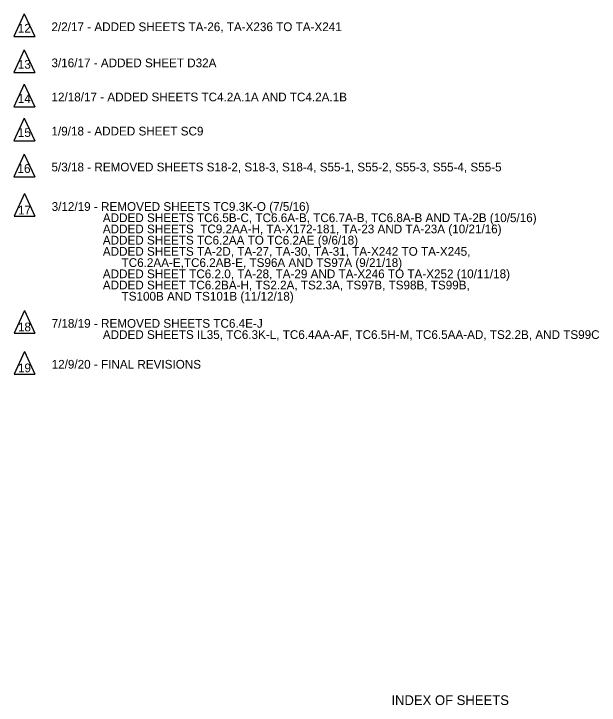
# Model space of a CAD drawing. Extents: x 116 to 2310, y 9 to 1131.
# Drawn here: x 1337.6 to 1756.2, y 112.9 to 607.5 of the extents above; entities that cross this region are included whole.
import ezdxf

# ---------------------------------------------------------------- set-up
doc = ezdxf.new("R2010")
doc.units = 0
for name, color, linetype in [('BR_AUTO DIMENSION', 7, 'Continuous'), ('BR_TEXT', 7, 'Continuous'), ('RD_SHT_TX', 7, 'Continuous'), ('RD_TX_RoadID', 7, 'Continuous')]:
    doc.layers.add(name, color=color, linetype=linetype)

msp = doc.modelspace()

# ---------------------------------------------------------------- linework, layer by layer
at = {"layer": 'BR_AUTO DIMENSION'}
for p, q in [((1345.07, 607.5), (1337.57, 591.27)), ((1345.07, 607.5), (1352.57, 591.27)), ((1337.57, 591.27), (1352.57, 591.27)), ((1345.07, 581.67), (1337.57, 565.43)), ((1345.07, 581.67), (1352.57, 565.43)), ((1337.57, 565.43), (1352.57, 565.43)), ((1345.07, 557.26), (1337.57, 541.02)), ((1345.07, 557.26), (1352.57, 541.02)), ((1337.57, 541.02), (1352.57, 541.02)), ((1345.07, 532.86), (1337.57, 516.62)), ((1345.07, 532.86), (1352.57, 516.62)), ((1337.57, 516.62), (1352.57, 516.62)), ((1345.07, 507.16), (1337.57, 490.92)), ((1345.07, 507.16), (1352.57, 490.92)), ((1337.57, 490.92), (1352.57, 490.92)), ((1345.2, 478.9), (1337.7, 462.67)), ((1345.2, 478.9), (1352.7, 462.67)), ((1337.7, 462.67), (1352.7, 462.67)), ((1345.2, 395.29), (1337.7, 379.05)), ((1345.2, 395.29), (1352.7, 379.05)), ((1337.7, 379.05), (1352.7, 379.05)), ((1345.2, 366.01), (1337.7, 349.78)), ((1345.2, 366.01), (1352.7, 349.78)), ((1337.7, 349.78), (1352.7, 349.78))]:
    msp.add_line(p, q, dxfattribs=at)

# ---------------------------------------------------------------- texts
at = {"layer": 'BR_TEXT'}
for s, p in [('12', (1340.43, 594.06)), ('13', (1340.43, 568.23)), ('14', (1340.43, 543.82)), ('15', (1340.43, 519.42)), ('16', (1340.2, 493.72)), ('17', (1340.51, 463.93)), ('18', (1340.51, 380.32)), ('19', (1340.51, 351.04))]:
    msp.add_text(s, height=6.25, dxfattribs=at).set_placement(p)
at = {"layer": 'RD_SHT_TX'}
for s, p in [('2/2/17 - ADDED SHEETS TA-26, TA-X236 TO TA-X241', (1364.49, 595.12)), ('3/16/17 - ADDED SHEET D32A', (1364.49, 569.28)), ('12/18/17 - ADDED SHEETS TC4.2A.1A AND TC4.2A.1B', (1364.49, 544.88)), ('1/9/18 - ADDED SHEET SC9', (1364.49, 520.47)), ('5/3/18 - REMOVED SHEETS S18-2, S18-3, S18-4, S55-1, S55-2, S55-3, S55-4, S55-5', (1364.49, 494.77)), ('3/12/19 - REMOVED SHEETS TC9.3K-O (7/5/16)', (1364.62, 466.52)), ('     ADDED SHEETS TC6.5B-C, TC6.6A-B, TC6.7A-B, TC6.8A-B AND TA-2B (10/5/16)', (1389.62, 458.49)), ('     ADDED SHEETS  TC9.2AA-H, TA-X172-181, TA-23 AND TA-23A (10/21/16)', (1389.62, 450.46)), ('     ADDED SHEETS TC6.2AA TO TC6.2AE (9/6/18)', (1389.62, 442.44)), ('     ADDED SHEETS TA-2D, TA-27, TA-30, TA-31, TA-X242 TO TA-X245, ', (1389.62, 434.41)), ('TC6.2AA-E,TC6.2AB-E, TS96A AND TS97A (9/21/18)', (1414.62, 426.38)), ('     ADDED SHEET TC6.2.0, TA-28, TA-29 AND TA-X246 TO TA-X252 (10/11/18)', (1389.62, 418.35)), ('     ADDED SHEET TC6.2BA-H, TS2.2A, TS2.3A, TS97B, TS98B, TS99B, ', (1389.62, 410.33)), ('TS100B AND TS101B (11/12/18)', (1414.62, 402.3)), ('7/18/19 - REMOVED SHEETS TC6.4E-J', (1364.62, 382.9)), ('     ADDED SHEETS IL35, TC6.3K-L, TC6.4AA-AF, TC6.5H-M, TC6.5AA-AD, TS2.2B, AND TS99C', (1389.62, 374.88)), ('12/9/20 - FINAL REVISIONS', (1364.62, 353.63))]:
    msp.add_text(s, height=6.2499, dxfattribs=at).set_placement(p)
at = {"layer": 'RD_TX_RoadID'}
msp.add_text('INDEX OF SHEETS', height=6.9833, dxfattribs=at).set_placement((1607.62, 112.97))

doc.saveas('drawing.dxf')
